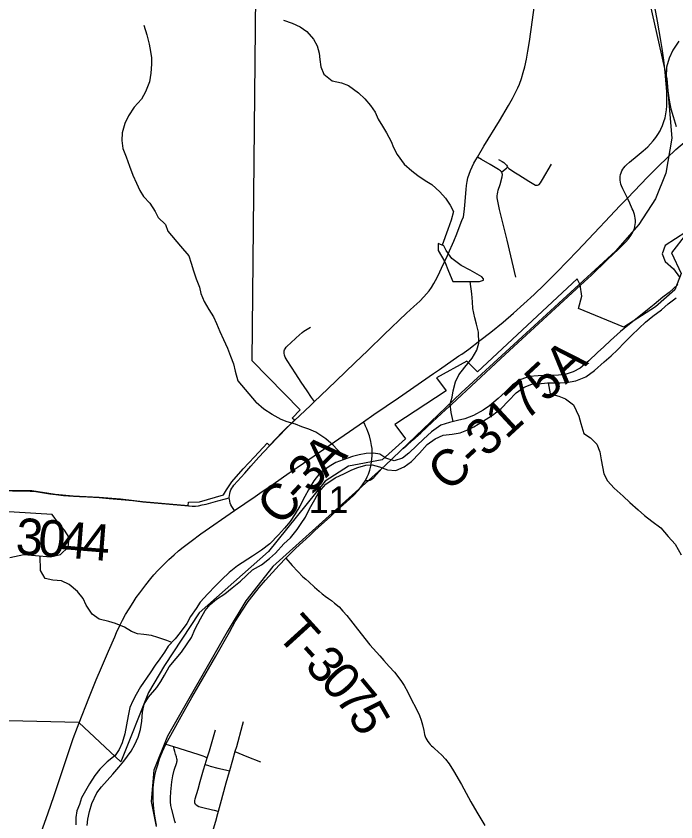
# Model space of a CAD drawing. Extents: x -7.5 to 53.5, y 0 to 22.
# Drawn here: x 2.688 to 3.721, y 15.27 to 16.532 of the extents above; entities that cross this region are included whole.
import ezdxf

# ---------------------------------------------------------------- set-up
doc = ezdxf.new("R2010")
doc.units = 0
for name, color, linetype in [('GM_X_City_Street', 7, 'Continuous'), ('GM_X_Corporation', 7, 'Continuous'), ('GM_X_County_Road', 7, 'Continuous'), ('GM_X_County_Road_Text', 7, 'Continuous'), ('GM_X_Major_River', 7, 'Continuous'), ('GM_X_Minor_Lake', 7, 'Continuous'), ('GM_X_Minor_River', 7, 'Continuous'), ('GM_X_Rail_Line', 7, 'Continuous'), ('GM_X_Section_Text', 7, 'Continuous'), ('GM_X_State_Route', 7, 'Continuous'), ('GM_X_Township_Road', 7, 'Continuous'), ('GM_X_Township_Road_Text', 7, 'Continuous')]:
    doc.layers.add(name, color=color, linetype=linetype)

msp = doc.modelspace()

# ---------------------------------------------------------------- linework, layer by layer
at = {"layer": 'GM_X_City_Street'}
for points in [[(3.4103, 16.3115), (3.4203, 16.3285), (3.4444, 16.3684), (3.4587, 16.3925), (3.4649, 16.4034), (3.4692, 16.4117), (3.4732, 16.4201), (3.4757, 16.4259), (3.4789, 16.4347), (3.4817, 16.4437), (3.4841, 16.4527), (3.4867, 16.4649), (3.489, 16.4772), (3.4913, 16.4926), (3.496, 16.5265), (3.5006, 16.5573)], [(3.6447, 16.247), (3.641, 16.2547), (3.6377, 16.2617), (3.6357, 16.2663), (3.6347, 16.2692), (3.634, 16.2722), (3.6336, 16.2751), (3.6335, 16.2782), (3.6336, 16.2812), (3.6341, 16.2841), (3.635, 16.287), (3.6361, 16.2898), (3.6375, 16.2924), (3.6393, 16.2949), (3.6412, 16.2972), (3.6434, 16.2994), (3.648, 16.3034), (3.6601, 16.3133), (3.6696, 16.3214), (3.6765, 16.3277), (3.6809, 16.3323), (3.6851, 16.337), (3.689, 16.3419), (3.6926, 16.3471), (3.6958, 16.3525), (3.6972, 16.3553), (3.6998, 16.3611), (3.7019, 16.367), (3.7036, 16.3731), (3.705, 16.3792), (3.7059, 16.3854), (3.7065, 16.3917), (3.7067, 16.3979), (3.7067, 16.4042), (3.7063, 16.4136), (3.7055, 16.426), (3.7038, 16.4446), (3.7018, 16.4632), (3.6993, 16.4817), (3.6973, 16.4939), (3.6918, 16.5244), (3.6862, 16.5551)], [(3.4703, 16.1235), (3.4564, 16.1811), (3.4498, 16.2084), (3.4447, 16.2296), (3.4413, 16.2448), (3.4409, 16.2477), (3.4409, 16.2507), (3.4413, 16.2537), (3.4419, 16.2567), (3.4427, 16.2597), (3.4454, 16.2687), (3.4487, 16.2807), (3.4491, 16.2841), (3.4489, 16.2858), (3.4483, 16.2875), (3.4478, 16.2881), (3.4473, 16.2888), (3.4461, 16.2901), (3.4433, 16.2919), (3.4299, 16.2999), (3.4165, 16.3079), (3.4103, 16.3115)], [(3.4433, 16.3077), (3.4486, 16.3045), (3.4512, 16.3028), (3.4535, 16.3009), (3.4556, 16.2986), (3.4565, 16.2974), (3.4573, 16.2959)], [(3.4478, 16.2881), (3.4509, 16.2906), (3.4554, 16.2943), (3.4573, 16.2959)], [(3.4573, 16.2959), (3.4581, 16.2948), (3.4593, 16.2938), (3.4694, 16.2869), (3.4747, 16.2837), (3.4904, 16.2739), (3.493, 16.2723), (3.4982, 16.269), (3.501, 16.2677), (3.5026, 16.2674), (3.5041, 16.2674), (3.5055, 16.2679), (3.5068, 16.2687), (3.5087, 16.2711), (3.5118, 16.2764), (3.5259, 16.3004)], [(3.155, 15.9288), (3.1506, 15.9351), (3.1435, 15.9453), (3.1342, 15.9591), (3.1257, 15.972), (3.1125, 15.9929), (3.1109, 15.9956), (3.1094, 15.9983), (3.1082, 16.0013), (3.1076, 16.0045), (3.1076, 16.0061), (3.1078, 16.0079), (3.1083, 16.0094), (3.1091, 16.011), (3.111, 16.0136), (3.1131, 16.0159), (3.1176, 16.0202), (3.1265, 16.0286), (3.131, 16.0328), (3.1358, 16.0368), (3.1384, 16.0386), (3.1489, 16.0453)]]:
    msp.add_lwpolyline(points, dxfattribs=at)
at = {"layer": 'GM_X_Corporation'}
for points in [[(2.6671, 15.7892), (2.713, 15.7891), (2.7492, 15.7837), (2.7777, 15.781), (2.8181, 15.7787), (2.8514, 15.776), (2.8862, 15.7722), (2.9576, 15.7658), (2.958, 15.771), (2.9753, 15.7714), (3.0125, 15.7826), (3.0176, 15.7902), (3.0257, 15.8029), (3.0435, 15.8232), (3.0614, 15.8421), (3.0811, 15.8636), (3.0846, 15.8599), (3.1045, 15.8806), (3.1238, 15.8994), (3.1202, 15.9028), (3.1328, 15.9157), (3.0578, 15.9924), (3.0636, 16.6178)], [(3.737, 16.1919), (3.7138, 16.1615), (3.729, 16.1293), (3.7192, 16.1034), (3.6888, 16.0767), (3.639, 16.0452), (3.5684, 16.0741), (3.5735, 16.0936), (3.571, 16.1114), (3.5659, 16.1208), (3.4102, 15.9749), (3.3933, 15.9918), (3.346, 15.966), (3.3611, 15.9454), (3.2808, 15.8927), (3.2977, 15.8704), (3.2611, 15.8374), (3.2082, 15.8272), (3.1717, 15.8039), (3.0831, 15.6935), (2.9746, 15.5977), (2.9205, 15.5154), (2.8954, 15.473), (2.8522, 15.3643), (2.7865, 15.4257), (2.5449, 15.4317)]]:
    msp.add_lwpolyline(points, dxfattribs=at)
at = {"layer": 'GM_X_County_Road'}
for points in [[(3.3779, 16.1914), (3.3817, 16.201), (3.3859, 16.2119), (3.3882, 16.218), (3.3895, 16.2255), (3.3906, 16.2354), (3.3915, 16.2485), (3.3922, 16.2609), (3.3929, 16.267), (3.3939, 16.273), (3.3953, 16.279), (3.3971, 16.2848), (3.3992, 16.2906), (3.4017, 16.2962), (3.4046, 16.3017), (3.4077, 16.307), (3.4103, 16.3115)], [(3.5712, 16.1109), (3.5885, 16.1268), (3.6133, 16.1503), (3.6311, 16.1676), (3.6423, 16.1786), (3.6463, 16.1834), (3.6501, 16.1885), (3.6518, 16.1912), (3.6533, 16.1939), (3.6546, 16.1968), (3.6557, 16.1998), (3.6565, 16.2029), (3.6571, 16.2061), (3.6574, 16.2092), (3.6574, 16.2124), (3.6571, 16.2156), (3.6566, 16.2187), (3.6558, 16.2218), (3.6548, 16.2248), (3.6537, 16.2278), (3.6524, 16.2306), (3.6483, 16.2392), (3.6447, 16.247)], [(3.3418, 16.1134), (3.3445, 16.118), (3.3487, 16.1259), (3.3541, 16.1373), (3.363, 16.1573), (3.3642, 16.16), (3.3729, 16.18), (3.3779, 16.1914)], [(3.2643, 16.0334), (3.2992, 16.0668), (3.3106, 16.0773), (3.3197, 16.0859), (3.3263, 16.0926), (3.3305, 16.0973), (3.3343, 16.1022), (3.338, 16.1073), (3.3418, 16.1134)], [(3.3085, 15.8679), (3.3213, 15.8797), (3.3399, 15.897), (3.3601, 15.9156), (3.3699, 15.9246), (3.4462, 15.9955), (3.4668, 16.0146), (3.5712, 16.1109)], [(3.155, 15.9288), (3.1644, 15.9377), (3.1891, 15.9613), (3.2183, 15.9893), (3.2385, 16.0087), (3.2643, 16.0334)], [(3.124, 15.8988), (3.1486, 15.9226), (3.155, 15.9288)], [(3.0848, 15.8594), (3.0983, 15.8736), (3.112, 15.8875), (3.124, 15.8988)], [(3.2443, 15.8341), (3.2452, 15.8435), (3.2455, 15.8492), (3.2451, 15.8549), (3.2445, 15.8599), (3.2434, 15.8661), (3.241, 15.8748), (3.2387, 15.8815), (3.2368, 15.8861), (3.235, 15.8901), (3.2332, 15.8942), (3.2318, 15.8968)], [(3.294, 15.8546), (3.2984, 15.8585), (3.3085, 15.8679)], [(3.0459, 15.8165), (3.0555, 15.8276), (3.0682, 15.8415), (3.0848, 15.8594)], [(3.2351, 15.805), (3.2374, 15.8107), (3.2394, 15.8151), (3.2415, 15.8212), (3.2433, 15.8275), (3.2443, 15.8341)], [(3.0218, 15.7777), (3.0218, 15.7785), (3.0219, 15.7815), (3.0224, 15.7844), (3.0231, 15.7873), (3.0242, 15.7901), (3.0256, 15.7927), (3.0273, 15.7952), (3.0291, 15.7976), (3.0459, 15.8165)], [(3.2351, 15.805), (3.238, 15.8049), (3.2401, 15.8051), (3.2421, 15.8055), (3.2441, 15.8066), (3.2455, 15.8076), (3.2478, 15.8096), (3.2563, 15.8189), (3.2585, 15.821)], [(3.1104, 15.6834), (3.1202, 15.6931), (3.1261, 15.6988), (3.1479, 15.719), (3.1547, 15.7256), (3.1615, 15.7317), (3.1795, 15.7482), (3.1839, 15.7524), (3.1908, 15.7586), (3.2046, 15.771), (3.2159, 15.7815), (3.224, 15.7898), (3.2277, 15.7943), (3.2314, 15.7995), (3.2351, 15.805)], [(3.0301, 15.7578), (3.0258, 15.7643), (3.0244, 15.7669), (3.0233, 15.7697), (3.0224, 15.7726), (3.022, 15.7755), (3.0218, 15.7777)], [(2.9226, 15.3918), (2.9328, 15.411), (2.9465, 15.4353), (2.9634, 15.4651), (2.9743, 15.484), (3.0005, 15.53), (3.0221, 15.5675), (3.0312, 15.5839), (3.0424, 15.602), (3.0513, 15.6152), (3.0589, 15.6252), (3.0687, 15.6374), (3.0786, 15.6491), (3.0998, 15.6724), (3.1104, 15.6834)], [(2.9078, 15.2652), (2.9062, 15.2737), (2.9047, 15.283), (2.9038, 15.291), (2.9032, 15.297), (2.903, 15.2998), (2.9028, 15.3027), (2.9027, 15.308), (2.9027, 15.3179), (2.9028, 15.3236), (2.9039, 15.3331), (2.9055, 15.3428), (2.9075, 15.3516), (2.9097, 15.3597), (2.9126, 15.3688), (2.9173, 15.3806), (2.9226, 15.3918)]]:
    msp.add_lwpolyline(points, dxfattribs=at)
at = {"layer": 'GM_X_Major_River'}
for points in [[(3.7253, 16.4931), (3.7159, 16.4787), (3.7102, 16.4665), (3.7057, 16.4521), (3.7054, 16.4365), (3.707, 16.4225), (3.7093, 16.4077), (3.7105, 16.3974), (3.7128, 16.3872), (3.7163, 16.3751), (3.7209, 16.3592)], [(3.736, 16.1941), (3.7039, 16.1731), (3.6994, 16.1602), (3.7037, 16.1477), (3.7167, 16.1364), (3.7263, 16.1236)], [(3.7238, 16.1118), (3.7102, 16.0995), (3.7004, 16.0919), (3.6865, 16.0804), (3.676, 16.0723), (3.6624, 16.0615), (3.6481, 16.05), (3.6338, 16.0381), (3.6184, 16.024), (3.6079, 16.0144), (3.5981, 16.0052), (3.5845, 15.9922), (3.5706, 15.981), (3.56, 15.9749), (3.5491, 15.9717), (3.537, 15.9697), (3.5176, 15.9695), (3.5051, 15.969), (3.4911, 15.9678), (3.4779, 15.9631), (3.465, 15.9546), (3.4541, 15.9439), (3.4425, 15.9332), (3.4289, 15.9217), (3.4191, 15.9151), (3.404, 15.907), (3.3901, 15.9016), (3.3787, 15.8988), (3.3666, 15.896), (3.353, 15.8914), (3.3383, 15.8814), (3.3259, 15.8695), (3.3153, 15.8599), (3.3026, 15.848), (3.2928, 15.84), (3.2799, 15.8357), (3.2666, 15.8401), (3.2571, 15.8461), (3.2472, 15.8479), (3.2362, 15.8474), (3.2252, 15.845), (3.2146, 15.8423), (3.1999, 15.8372), (3.1885, 15.8329), (3.178, 15.8268), (3.1637, 15.8164), (3.1543, 15.8045), (3.1457, 15.7904), (3.1401, 15.7797), (3.1323, 15.7649), (3.1248, 15.7527), (3.117, 15.7405), (3.1083, 15.7301), (3.0986, 15.7198), (3.085, 15.706), (3.0722, 15.6956), (3.0583, 15.6864)], [(3.0581, 15.6652), (3.0721, 15.6729), (3.0845, 15.6829), (3.0943, 15.6909), (3.107, 15.7055), (3.1176, 15.7154), (3.1281, 15.728), (3.134, 15.7376), (3.1408, 15.7475), (3.1475, 15.7605), (3.1557, 15.775), (3.1617, 15.7868), (3.1729, 15.799), (3.1872, 15.809), (3.202, 15.816), (3.2133, 15.8218), (3.2231, 15.8253), (3.2352, 15.8292), (3.2451, 15.8297), (3.2569, 15.8264), (3.2694, 15.8219), (3.2823, 15.8205), (3.2952, 15.8263), (3.3069, 15.8348), (3.3192, 15.8478), (3.3313, 15.8612), (3.3437, 15.87), (3.3565, 15.8758), (3.3706, 15.8775), (3.383, 15.8795), (3.3933, 15.8838), (3.4046, 15.8888), (3.4182, 15.8973), (3.4336, 15.9073), (3.4472, 15.9177), (3.4588, 15.9295), (3.4708, 15.9422), (3.4833, 15.951), (3.495, 15.9557), (3.5052, 15.9565), (3.5196, 15.9578), (3.5397, 15.958), (3.5492, 15.9584), (3.564, 15.9608), (3.5795, 15.9674), (3.5934, 15.9774), (3.6084, 15.9909), (3.6194, 16.0004), (3.6295, 16.0096), (3.6404, 16.0211), (3.6513, 16.0322), (3.663, 16.0437), (3.6731, 16.0529), (3.6848, 16.0625), (3.698, 16.0725), (3.7085, 16.0817), (3.7209, 16.0909)], [(3.0583, 15.6864), (3.0345, 15.6711), (3.0216, 15.6609), (3.0102, 15.6499), (3, 15.64), (2.9883, 15.6275), (2.9762, 15.6146), (2.9697, 15.6047), (2.961, 15.5918), (2.9554, 15.5808), (2.9448, 15.5667), (2.9372, 15.5572), (2.9262, 15.5455), (2.9205, 15.536), (2.9133, 15.5257), (2.9058, 15.5155), (2.8978, 15.5037), (2.8827, 15.4817), (2.8759, 15.47), (2.8706, 15.4601), (2.866, 15.4495), (2.8634, 15.4362), (2.8608, 15.4222), (2.8585, 15.4081), (2.8543, 15.3941), (2.8494, 15.3835), (2.843, 15.374), (2.8305, 15.3641), (2.8191, 15.3531), (2.8112, 15.3428), (2.8032, 15.3299), (2.7968, 15.3189), (2.7907, 15.3079), (2.7873, 15.2977), (2.7832, 15.2878), (2.7817, 15.2772), (2.7817, 15.2655)], [(2.7995, 15.2647), (2.8006, 15.2746), (2.8029, 15.2867), (2.8067, 15.2992), (2.8146, 15.3156), (2.8218, 15.3254), (2.8305, 15.3353), (2.8396, 15.3448), (2.8491, 15.3558), (2.8566, 15.3653), (2.868, 15.3812), (2.8737, 15.3915), (2.879, 15.4032), (2.8827, 15.415), (2.885, 15.4279), (2.8857, 15.4423), (2.8884, 15.4548), (2.8952, 15.4658), (2.9085, 15.4806), (2.9145, 15.4901), (2.9202, 15.5003), (2.9278, 15.5133), (2.9384, 15.5262), (2.9471, 15.536), (2.9561, 15.5493), (2.9626, 15.5592), (2.9682, 15.5725), (2.9769, 15.5884), (2.9838, 15.6013), (2.9917, 15.6108), (3.0016, 15.6191), (3.0148, 15.6275), (3.0262, 15.6366), (3.0391, 15.6472), (3.0581, 15.6652)]]:
    msp.add_lwpolyline(points, dxfattribs=at)
at = {"layer": 'GM_X_Minor_Lake'}
for points in [[(3.4168, 16.1238), (3.3988, 16.1346), (3.3844, 16.1418), (3.37, 16.1526), (3.361, 16.1652), (3.3574, 16.1724), (3.3484, 16.176), (3.3484, 16.1652), (3.3592, 16.1472), (3.3646, 16.1328), (3.3718, 16.1166)], [(3.3718, 16.1166), (3.4132, 16.1166)], [(3.4132, 16.1166), (3.4195, 16.1187), (3.4195, 16.1209), (3.4168, 16.1238)], [(2.6785, 15.6843), (2.7005, 15.6889), (2.7187, 15.6877), (2.7422, 15.6855), (2.7577, 15.6893), (2.7695, 15.7007), (2.7714, 15.7155), (2.7638, 15.7272), (2.7554, 15.7367), (2.7444, 15.7519), (2.6167, 15.7596), (2.6106, 15.7551), (2.6114, 15.746), (2.6174, 15.7399), (2.6288, 15.7396), (2.6371, 15.7373), (2.6372, 15.7308), (2.6398, 15.7214)]]:
    msp.add_lwpolyline(points, dxfattribs=at)
at = {"layer": 'GM_X_Minor_River'}
for points in [[(3.1067, 16.5257), (3.1199, 16.5212), (3.1325, 16.5155), (3.1431, 16.5084), (3.1538, 16.4963), (3.1595, 16.4857), (3.1626, 16.4743), (3.1634, 16.4644), (3.1649, 16.453), (3.1695, 16.4413), (3.1829, 16.4307), (3.1976, 16.4277), (3.2083, 16.4236), (3.2242, 16.4123), (3.2338, 16.4028), (3.2425, 16.3922), (3.2498, 16.3816), (3.2547, 16.371), (3.2616, 16.3597), (3.2677, 16.3495), (3.2753, 16.3358), (3.2788, 16.3264), (3.2845, 16.3154), (3.2952, 16.3006), (3.3074, 16.2897), (3.3169, 16.2825), (3.3283, 16.2746), (3.3389, 16.2685), (3.3511, 16.2568), (3.3602, 16.247), (3.3675, 16.2364), (3.3724, 16.2265), (3.3691, 16.2125), (3.3635, 16.198), (3.3547, 16.1735)], [(2.8882, 16.5183), (2.8928, 16.5028), (2.8962, 16.4883), (2.8985, 16.4769), (2.9, 16.4667), (2.8999, 16.4568), (2.8988, 16.4428), (2.8969, 16.4291), (2.8908, 16.4139), (2.8843, 16.4021), (2.8729, 16.3896), (2.8642, 16.3763), (2.8585, 16.3642), (2.8539, 16.3494), (2.8535, 16.3372), (2.8554, 16.3251), (2.8603, 16.3118), (2.8656, 16.2973), (2.8709, 16.2833), (2.8766, 16.2708), (2.8819, 16.2594), (2.8876, 16.2495), (2.8974, 16.2392), (2.9058, 16.2263), (2.9107, 16.2168), (2.9217, 16.2058), (2.9255, 16.1952)], [(2.9255, 16.1952), (2.9453, 16.1722), (2.9582, 16.1567), (2.962, 16.1453), (2.9658, 16.1332), (2.9699, 16.1207), (2.9749, 16.1078), (2.9772, 16.098), (2.9825, 16.0855), (2.9897, 16.073), (2.9969, 16.0612), (3.0019, 16.051), (3.0068, 16.0385), (3.0125, 16.026), (3.019, 16.0123), (3.0239, 15.9998), (3.0281, 15.9877), (3.0311, 15.976), (3.0353, 15.9608), (3.0637, 15.927)], [(3.3723, 15.8973), (3.3691, 15.9112), (3.3675, 15.9249), (3.3704, 15.9355), (3.3722, 15.9454), (3.3755, 15.9595), (3.3811, 15.9705), (3.3901, 15.9824), (3.4017, 15.9965), (3.4092, 16.0091), (3.4125, 16.0202), (3.4116, 16.0372), (3.4088, 16.0497), (3.4061, 16.0596), (3.4029, 16.0743), (3.4021, 16.0849), (3.4012, 16.0975), (3.3988, 16.1166)], [(3.5208, 15.9578), (3.5239, 15.9407), (3.5376, 15.9371), (3.5479, 15.933), (3.5605, 15.9233), (3.569, 15.9059), (3.5718, 15.8941), (3.5768, 15.8786), (3.5871, 15.8719), (3.5971, 15.8617), (3.6014, 15.8496), (3.6038, 15.8375), (3.6077, 15.8156), (3.6135, 15.8046), (3.6243, 15.7929), (3.638, 15.7802), (3.6487, 15.7704), (3.6617, 15.7591), (3.6717, 15.7501), (3.6831, 15.7415), (3.6969, 15.731), (3.7087, 15.7175), (3.7195, 15.7054), (3.7291, 15.6884)], [(3.2005, 15.8374), (3.1972, 15.8463), (3.1845, 15.8602), (3.173, 15.8704), (3.157, 15.8805), (3.146, 15.8853), (3.1353, 15.889), (3.1254, 15.8931), (3.1125, 15.8967), (3.103, 15.9004), (3.0889, 15.9083), (3.0759, 15.9165), (3.0637, 15.927)], [(2.9317, 15.5514), (2.9239, 15.5546), (2.9099, 15.5591), (2.9, 15.5621), (2.8883, 15.5636), (2.878, 15.5647), (2.8686, 15.5685), (2.8576, 15.575), (2.8435, 15.581), (2.8333, 15.584), (2.8181, 15.5878), (2.8071, 15.5957), (2.798, 15.6097), (2.7931, 15.6204), (2.7843, 15.631), (2.7714, 15.6423), (2.7593, 15.6476), (2.7457, 15.6491), (2.7339, 15.6514), (2.7263, 15.6639), (2.726, 15.687)]]:
    msp.add_lwpolyline(points, dxfattribs=at)
at = {"layer": 'GM_X_Rail_Line'}
msp.add_lwpolyline([(3.2081, 17.7847), (3.2418, 17.7434), (3.2623, 17.7157), (3.291, 17.6735), (3.3451, 17.5787), (3.5229, 17.1533), (3.5905, 16.9386), (3.633, 16.7607), (3.7064, 16.4339), (3.7141, 16.341), (3.7047, 16.2861), (3.6889, 16.2462), (3.6625, 16.2061), (3.6262, 16.1639), (3.3846, 15.9423), (3.2658, 15.8286), (3.0899, 15.67), (3.0475, 15.6167), (3.0184, 15.5677), (2.9253, 15.4046), (2.9035, 15.3511), (2.8997, 15.3022), (2.9073, 15.2631)], dxfattribs=at)
at = {"layer": 'GM_X_State_Route'}
for points in [[(3.61, 16.2106), (3.633, 16.2349), (3.6447, 16.247), (3.6761, 16.2798), (3.6936, 16.2975), (3.707, 16.3105), (3.7208, 16.3231), (3.7371, 16.3375), (3.7464, 16.3455)], [(2.8425, 15.5603), (2.8453, 15.5667), (2.8506, 15.5779), (2.8549, 15.5862), (2.8596, 15.5951), (2.865, 15.6042), (2.8711, 15.6139), (2.8762, 15.6217), (2.8817, 15.6292), (2.8912, 15.6415), (2.8991, 15.6513), (2.9037, 15.6571), (2.9098, 15.6639), (2.9162, 15.6705), (2.9272, 15.6811), (2.9353, 15.6883), (2.9424, 15.6946), (2.9497, 15.7006), (2.9621, 15.7101), (2.9773, 15.7212), (3.0301, 15.7578), (3.0623, 15.7801), (3.0694, 15.7852), (3.0904, 15.7994), (3.1155, 15.8167), (3.1281, 15.8253), (3.138, 15.8322), (3.2097, 15.8816), (3.2318, 15.8968), (3.2481, 15.9081), (3.2866, 15.9345), (3.3415, 15.9724), (3.3505, 15.9787), (3.3812, 16), (3.3855, 16.003), (3.3964, 16.0108), (3.4137, 16.024), (3.4308, 16.0374), (3.4501, 16.0531), (3.4666, 16.0672), (3.4829, 16.0817), (3.4989, 16.0965), (3.5145, 16.1116), (3.5342, 16.1314), (3.5667, 16.1649), (3.601, 16.201), (3.61, 16.2106)], [(2.7867, 15.4252), (2.802, 15.4643), (2.8135, 15.493), (2.8216, 15.5119), (2.8325, 15.5374), (2.8425, 15.5603)], [(2.7591, 15.3458), (2.7693, 15.376), (2.7777, 15.4008), (2.7842, 15.4186), (2.7867, 15.4252)], [(2.5363, 14.8769), (2.5394, 14.8838), (2.5763, 14.9672), (2.5895, 14.9954), (2.6005, 15.0178), (2.6105, 15.0372), (2.6195, 15.0536), (2.6303, 15.0725), (2.6447, 15.0966), (2.6582, 15.1188), (2.6609, 15.1232), (2.6629, 15.1265), (2.6913, 15.1738), (2.6975, 15.1846), (2.7033, 15.1955), (2.7073, 15.2038), (2.7124, 15.2151), (2.7201, 15.2332), (2.728, 15.2552), (2.7379, 15.2828), (2.7477, 15.3118), (2.7591, 15.3458)]]:
    msp.add_lwpolyline(points, dxfattribs=at)
at = {"layer": 'GM_X_Township_Road'}
msp.add_line((2.9839, 15.3599), (2.9874, 15.3707), dxfattribs=at)
for points in [[(2.6823, 15.7887), (2.6887, 15.7887), (2.7009, 15.7888), (2.7102, 15.7885), (2.7189, 15.7875), (2.7286, 15.7861), (2.7409, 15.7843), (2.7501, 15.783), (2.7624, 15.7817), (2.778, 15.7805), (2.7873, 15.7799), (2.7997, 15.7792), (2.8183, 15.7781), (2.8338, 15.777), (2.8524, 15.7754), (2.8709, 15.7734), (2.8864, 15.7717), (2.9578, 15.7653), (2.9588, 15.7652)], [(2.9588, 15.7652), (2.9636, 15.765), (2.9691, 15.765), (2.9737, 15.7654), (2.9794, 15.7666), (2.9856, 15.768), (3.0038, 15.7731), (3.016, 15.7762), (3.0218, 15.7777)], [(3.1104, 15.6834), (3.1202, 15.6719), (3.129, 15.6625), (3.1369, 15.6543), (3.1415, 15.6502), (3.1461, 15.646), (3.1552, 15.6377), (3.1622, 15.6316), (3.1669, 15.6277), (3.1693, 15.6258), (3.1718, 15.624), (3.1768, 15.6204), (3.1818, 15.6168), (3.1866, 15.613), (3.1936, 15.6069), (3.1994, 15.6002), (3.2056, 15.5933), (3.2115, 15.5862), (3.2152, 15.5813), (3.2226, 15.572), (3.2419, 15.5474), (3.2523, 15.5359), (3.2574, 15.5306), (3.2638, 15.5231), (3.272, 15.5139), (3.2802, 15.5047), (3.2902, 15.4916), (3.2952, 15.4839), (3.301, 15.4733), (3.3052, 15.4648), (3.3151, 15.4458), (3.3193, 15.437), (3.3221, 15.4296), (3.324, 15.4225), (3.326, 15.4132), (3.3275, 15.4072), (3.3284, 15.404), (3.3293, 15.4013), (3.3308, 15.3988), (3.3325, 15.3963), (3.3343, 15.3938), (3.3361, 15.3915), (3.3381, 15.3894), (3.3401, 15.3877), (3.3423, 15.3858), (3.3492, 15.3795), (3.3536, 15.3751), (3.36, 15.3683), (3.3656, 15.3611), (3.3724, 15.3504), (3.3849, 15.3287), (3.4, 15.3017), (3.4092, 15.2856), (3.4138, 15.2776), (3.4214, 15.2645)], [(3.0434, 15.427), (3.0419, 15.421), (3.0328, 15.3879), (3.0307, 15.3805)], [(2.9874, 15.3707), (2.9908, 15.3815), (3.0003, 15.4145)], [(2.9226, 15.3918), (2.9279, 15.3904), (2.9344, 15.3883)], [(2.9375, 15.2685), (2.9365, 15.2715), (2.9317, 15.2896), (2.9305, 15.2957), (2.9298, 15.3019), (2.9298, 15.3081), (2.9304, 15.3174), (2.9316, 15.333), (2.9332, 15.3422), (2.9355, 15.3512), (2.9395, 15.3631), (2.9399, 15.3644), (2.9401, 15.3661), (2.94, 15.3677), (2.9398, 15.3692), (2.9389, 15.3722), (2.9375, 15.3763), (2.9363, 15.3806), (2.9353, 15.384), (2.9344, 15.3883)], [(2.9344, 15.3883), (2.9724, 15.3761), (2.9804, 15.3737), (2.9831, 15.3725), (2.9874, 15.3707)], [(3.0307, 15.3805), (3.0269, 15.3669), (3.0221, 15.3501)], [(3.0307, 15.3805), (3.0493, 15.3729), (3.0705, 15.3643)], [(3.0043, 15.2865), (2.9984, 15.288), (2.9954, 15.2888), (2.9802, 15.2923), (2.9742, 15.2941), (2.9713, 15.2954), (2.969, 15.2975), (2.9678, 15.3003), (2.9677, 15.3035), (2.9684, 15.3065), (2.973, 15.3215), (2.9762, 15.3336), (2.9813, 15.3516), (2.9839, 15.3599)], [(2.9839, 15.3599), (2.9891, 15.3584), (2.992, 15.3575), (3.0038, 15.3544), (3.0157, 15.3516), (3.0221, 15.3501)], [(3.0221, 15.3501), (3.0218, 15.3489), (3.0166, 15.3309), (3.0076, 15.2979), (3.0043, 15.2865)], [(3.0043, 15.2865), (3.0032, 15.2829), (3, 15.2708), (2.9966, 15.2588)]]:
    msp.add_lwpolyline(points, dxfattribs=at)

# ---------------------------------------------------------------- texts
at = {"layer": 'GM_X_County_Road_Text'}
for s, height, rotation, p in [('C-3175A', 0.05682, 42.7822, (3.3651, 15.7852)), ('A', 0.0568, 45.1494, (3.1731, 15.8079)), ('3', 0.0568, 46.1666, (3.1491, 15.7829)), ('C', 0.0568, 47.8741, (3.1022, 15.7315)), ('-', 0.0568, 47.0316, (3.1333, 15.766))]:
    msp.add_text(s, height=height, rotation=rotation, dxfattribs=at).set_placement(p)
at = {"layer": 'GM_X_Section_Text'}
msp.add_text('11', height=0.04186, rotation=0, dxfattribs=at).set_placement((3.1461, 15.754))
at = {"layer": 'GM_X_Township_Road_Text'}
for s, rotation, p in [('3', 356.3808, (2.6865, 15.6898)), ('0', 355.6089, (2.7212, 15.6876)), ('4', 355.4001, (2.7561, 15.6849)), ('4', 355.353, (2.7909, 15.6821)), ('T', 312.3019, (3.0937, 15.5626)), ('-', 312.3, (3.1223, 15.5312)), ('3', 312.3757, (3.138, 15.5138)), ('0', 312.9585, (3.162, 15.4875)), ('7', 309.6343, (3.1853, 15.4626)), ('5', 299.874, (3.2062, 15.4377))]:
    msp.add_text(s, height=0.0568, rotation=rotation, dxfattribs=at).set_placement(p)

doc.saveas('drawing.dxf')
